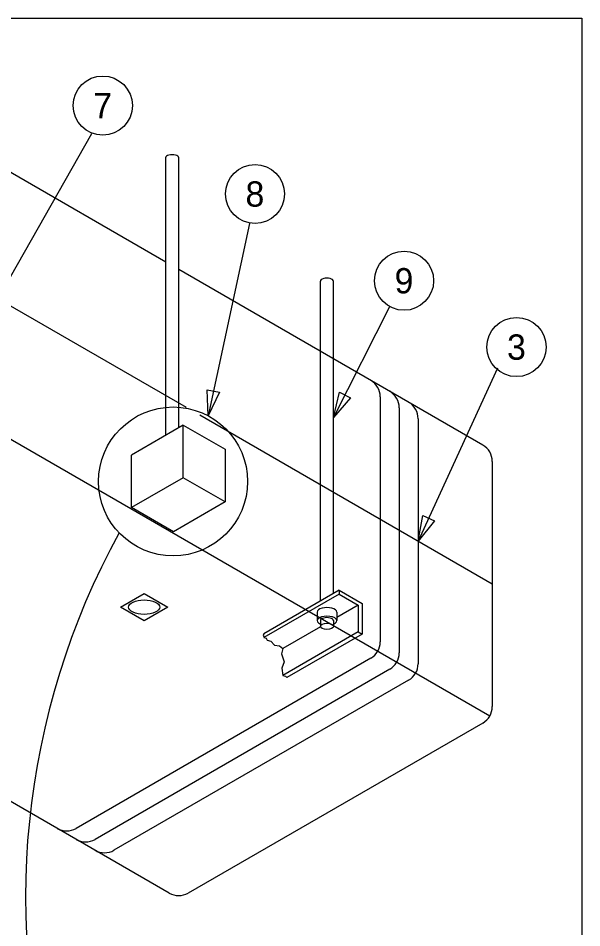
# Model space of a CAD drawing. Extents: x 10110.2 to 10159.4, y 10049.5 to 10140.5.
# Drawn here: x 10144.51 to 10159.36, y 10116.52 to 10140.51 of the extents above; entities that cross this region are included whole.
import ezdxf

# ---------------------------------------------------------------- set-up
doc = ezdxf.new("R2010")
doc.units = 0
for name, color, linetype in [('G-ANNO-SYMB', 7, 'Continuous'), ('G-DETL-GRID', 7, 'Continuous'), ('G-DETL-LINE', 7, 'Continuous'), ('G-DETL-TEXT', 7, 'Continuous')]:
    doc.layers.add(name, color=color, linetype=linetype)

msp = doc.modelspace()

# ---------------------------------------------------------------- linework, layer by layer
at = {"layer": 'G-ANNO-SYMB'}
for centre in [(10146.738, 10138.202), (10150.75, 10135.871), (10154.678, 10133.583), (10157.641, 10131.834)]:
    msp.add_circle(centre, 0.779, dxfattribs=at)
at = {"layer": 'G-DETL-GRID'}
msp.add_lwpolyline([(10110.22, 10140.505), (10159.362, 10140.505), (10159.362, 10095.005), (10110.22, 10095.005)], close=True, dxfattribs=at)
at = {"layer": 'G-DETL-LINE'}
for p, q in [((10148.395, 10134.077), (10142.598, 10137.424)), ((10148.395, 10134.077), (10142.598, 10137.424)), ((10148.395, 10129.51), (10148.395, 10136.827)), ((10148.395, 10129.51), (10148.395, 10136.827)), ((10148.74, 10129.709), (10148.74, 10136.827)), ((10148.947, 10130.239), (10142.598, 10133.904)), ((10148.947, 10130.239), (10142.598, 10133.904)), ((10156.752, 10129.252), (10148.74, 10133.878)), ((10156.752, 10129.252), (10148.74, 10133.878)), ((10152.474, 10131.722), (10152.474, 10133.573)), ((10152.474, 10131.722), (10152.474, 10133.573)), ((10152.819, 10131.523), (10152.819, 10133.573)), ((10152.819, 10131.523), (10152.819, 10133.573)), ((10152.474, 10125.141), (10152.474, 10131.722)), ((10152.474, 10125.141), (10152.474, 10131.722)), ((10152.819, 10125.34), (10152.819, 10131.523)), ((10152.819, 10125.34), (10152.819, 10131.523)), ((10154.049, 10130.524), (10154.049, 10124.062)), ((10154.049, 10130.524), (10154.049, 10124.062)), ((10154.549, 10130.235), (10154.549, 10123.773)), ((10154.549, 10130.235), (10154.549, 10123.773)), ((10156.935, 10122.107), (10142.888, 10130.217)), ((10156.935, 10122.107), (10142.888, 10130.217)), ((10157.002, 10125.588), (10149.292, 10130.039)), ((10157.002, 10125.588), (10149.292, 10130.039)), ((10148.859, 10129.778), (10147.493, 10128.989)), ((10148.859, 10129.778), (10147.493, 10128.989)), ((10155.049, 10129.947), (10155.049, 10123.485)), ((10155.049, 10129.947), (10155.049, 10123.485)), ((10147.493, 10127.602), (10147.493, 10128.989)), ((10147.493, 10127.602), (10147.493, 10128.989)), ((10157.002, 10128.819), (10157.002, 10122.357)), ((10157.002, 10128.819), (10157.002, 10122.357)), ((10148.859, 10128.39), (10147.493, 10127.602)), ((10148.859, 10128.39), (10147.493, 10127.602)), ((10148.598, 10126.964), (10147.493, 10127.602)), ((10148.598, 10126.964), (10147.493, 10127.602)), ((10149.963, 10127.753), (10148.598, 10126.964)), ((10149.963, 10127.753), (10148.598, 10126.964)), ((10148.487, 10117.44), (10134.623, 10125.445)), ((10148.487, 10117.44), (10134.623, 10125.445)), ((10152.97, 10125.427), (10150.981, 10124.279)), ((10152.97, 10125.427), (10150.981, 10124.279)), ((10152.97, 10125.427), (10153.574, 10125.078)), ((10152.97, 10125.427), (10152.97, 10125.323)), ((10152.97, 10125.427), (10153.574, 10125.078)), ((10152.97, 10125.427), (10152.97, 10125.323)), ((10152.97, 10125.323), (10150.981, 10124.175)), ((10152.97, 10125.323), (10150.981, 10124.175)), ((10152.97, 10125.323), (10153.47, 10125.034)), ((10152.97, 10125.323), (10153.47, 10125.034)), ((10153.47, 10125.034), (10152.905, 10124.708)), ((10153.47, 10125.034), (10152.905, 10124.708)), ((10153.47, 10125.034), (10153.47, 10124.328)), ((10153.47, 10125.034), (10153.47, 10124.328)), ((10153.574, 10125.078), (10153.574, 10124.268)), ((10153.574, 10125.078), (10153.574, 10124.268)), ((10152.387, 10124.847), (10152.387, 10124.622)), ((10152.387, 10124.847), (10152.387, 10124.622)), ((10152.905, 10124.847), (10152.905, 10124.622)), ((10152.905, 10124.847), (10152.905, 10124.622)), ((10152.474, 10124.622), (10152.474, 10124.472)), ((10152.474, 10124.622), (10152.474, 10124.472)), ((10152.819, 10124.622), (10152.819, 10124.472)), ((10152.819, 10124.622), (10152.819, 10124.472)), ((10150.981, 10124.279), (10150.962, 10124.227)), ((10150.981, 10124.279), (10150.962, 10124.227)), ((10152.476, 10124.46), (10151.481, 10123.886)), ((10152.476, 10124.46), (10151.481, 10123.886)), ((10153.47, 10124.328), (10151.481, 10123.18)), ((10153.47, 10124.328), (10151.481, 10123.18)), ((10153.574, 10124.268), (10151.586, 10123.12)), ((10153.574, 10124.268), (10151.586, 10123.12)), ((10153.47, 10124.328), (10153.574, 10124.268)), ((10153.47, 10124.328), (10153.574, 10124.268)), ((10150.962, 10124.227), (10150.979, 10124.202)), ((10150.962, 10124.227), (10150.979, 10124.202)), ((10150.979, 10124.202), (10150.992, 10124.185)), ((10150.979, 10124.202), (10150.992, 10124.185)), ((10150.992, 10124.185), (10150.981, 10124.175)), ((10150.992, 10124.185), (10150.981, 10124.175)), ((10150.981, 10124.175), (10151.043, 10124.158)), ((10150.981, 10124.175), (10151.043, 10124.158)), ((10151.043, 10124.158), (10151.073, 10124.111)), ((10151.043, 10124.158), (10151.073, 10124.111)), ((10151.073, 10124.111), (10151.163, 10124.082)), ((10151.073, 10124.111), (10151.163, 10124.082)), ((10151.163, 10124.082), (10151.263, 10123.973)), ((10151.163, 10124.082), (10151.263, 10123.973)), ((10151.263, 10123.973), (10151.395, 10123.957)), ((10151.263, 10123.973), (10151.395, 10123.957)), ((10151.395, 10123.957), (10151.481, 10123.886)), ((10151.395, 10123.957), (10151.481, 10123.886)), ((10151.481, 10123.886), (10151.45, 10123.745)), ((10151.481, 10123.886), (10151.45, 10123.745)), ((10153.799, 10123.629), (10146.033, 10119.146)), ((10153.799, 10123.629), (10146.033, 10119.146)), ((10151.45, 10123.745), (10151.518, 10123.541)), ((10151.45, 10123.745), (10151.518, 10123.541)), ((10151.518, 10123.541), (10151.458, 10123.371)), ((10151.518, 10123.541), (10151.458, 10123.371)), ((10154.299, 10123.34), (10146.533, 10118.857)), ((10154.299, 10123.34), (10146.533, 10118.857)), ((10151.458, 10123.371), (10151.481, 10123.18)), ((10151.458, 10123.371), (10151.481, 10123.18)), ((10154.799, 10123.052), (10147.033, 10118.568)), ((10154.799, 10123.052), (10147.033, 10118.568)), ((10151.481, 10123.18), (10151.549, 10123.162)), ((10151.481, 10123.18), (10151.549, 10123.162)), ((10151.549, 10123.162), (10151.586, 10123.12)), ((10151.549, 10123.162), (10151.586, 10123.12)), ((10156.752, 10121.924), (10148.987, 10117.44)), ((10156.752, 10121.924), (10148.987, 10117.44))]:
    msp.add_line(p, q, dxfattribs=at)
for points in [[(10149.963, 10127.753), (10148.859, 10128.39), (10148.859, 10129.778), (10149.963, 10129.14)], [(10149.963, 10127.753), (10148.859, 10128.39), (10148.859, 10129.778), (10149.963, 10129.14)], [(10147.207, 10124.979), (10147.828, 10125.338), (10148.449, 10124.979), (10147.828, 10124.62)], [(10147.207, 10124.979), (10147.828, 10125.338), (10148.449, 10124.979), (10147.828, 10124.62)]]:
    msp.add_lwpolyline(points, close=True, dxfattribs=at)
for centre, start, end in [((10153.549, 10130.524), 0, 60), ((10153.549, 10130.524), 0, 60), ((10154.049, 10130.235), 0, 60), ((10154.049, 10130.235), 0, 60), ((10154.549, 10129.947), 0, 60), ((10154.549, 10129.947), 0, 60), ((10156.502, 10128.819), 0, 60), ((10156.502, 10128.819), 0, 60), ((10153.549, 10124.062), 300, 360), ((10153.549, 10124.062), 300, 360), ((10154.049, 10123.773), 300, 360), ((10154.049, 10123.773), 300, 360), ((10154.549, 10123.485), 300, 360), ((10154.549, 10123.485), 300, 360), ((10156.502, 10122.357), 300, 360), ((10156.502, 10122.357), 300, 360), ((10145.783, 10119.579), 240, 300.0001), ((10145.783, 10119.579), 240, 300.0001), ((10146.283, 10119.29), 240, 300.0001), ((10146.283, 10119.29), 240, 300.0001), ((10146.783, 10119.002), 240, 300.0001), ((10146.783, 10119.002), 240, 300.0001), ((10148.737, 10117.874), 240, 300.0001), ((10148.737, 10117.874), 240, 300.0001)]:
    msp.add_arc(centre, 0.5, start, end, dxfattribs=at)
for centre, major_axis, start_param, end_param in [((10148.567, 10136.827), (-0.173, 0), 3.137491, 6.287287), ((10148.567, 10136.827), (-0.173, 0), 3.137491, 6.287287), ((10152.646, 10133.573), (-0.173, 0), 3.137491, 6.287287), ((10152.646, 10133.573), (-0.173, 0), 3.137491, 6.287287), ((10152.646, 10124.847), (-0.259, 0), 3.137491, 6.287287), ((10152.646, 10124.847), (-0.259, 0), 3.137491, 6.287287), ((10152.646, 10124.622), (-0.259, 0), 2.300516, 7.124262), ((10152.646, 10124.622), (-0.259, 0), 2.300516, 7.124262), ((10152.646, 10124.622), (-0.173, 0), 3.137491, 6.287287), ((10152.646, 10124.622), (-0.173, 0), 3.137491, 6.287287)]:
    msp.add_ellipse(centre, major_axis=major_axis, ratio=0.460797, start_param=start_param, end_param=end_param, dxfattribs=at)
for centre, major_axis in [((10147.828, 10124.979), (-0.413, 0)), ((10147.828, 10124.979), (-0.413, 0)), ((10152.646, 10124.472), (-0.173, 0)), ((10152.646, 10124.472), (-0.173, 0))]:
    msp.add_ellipse(centre, major_axis=major_axis, ratio=0.460797, dxfattribs=at)
at = {"layer": 'G-DETL-TEXT'}
for p, q in [((10146.44, 10137.459), (10143.032, 10131.459)), ((10146.44, 10137.459), (10143.032, 10131.459)), ((10150.6, 10135.093), (10149.516, 10130.025)), ((10150.6, 10135.093), (10149.516, 10130.025)), ((10154.307, 10132.91), (10152.819, 10129.977)), ((10154.307, 10132.91), (10152.819, 10129.977)), ((10157.143, 10131.283), (10155.049, 10126.716)), ((10157.143, 10131.283), (10155.049, 10126.716))]:
    msp.add_line(p, q, dxfattribs=at)
for points in [[(10149.818, 10130.642), (10149.516, 10130.025), (10149.492, 10130.711)], [(10149.818, 10130.642), (10149.516, 10130.025), (10149.492, 10130.711)], [(10153.269, 10130.496), (10152.819, 10129.977), (10152.972, 10130.647)], [(10153.269, 10130.496), (10152.819, 10129.977), (10152.972, 10130.647)], [(10155.478, 10127.252), (10155.049, 10126.716), (10155.175, 10127.391)], [(10155.478, 10127.252), (10155.049, 10126.716), (10155.175, 10127.391)]]:
    msp.add_lwpolyline(points, close=True, dxfattribs=at)
msp.add_circle((10148.591, 10128.291), 1.964, dxfattribs=at)
msp.add_arc((10164.714, 10117.308), 20.014, 151.243, 197.1832, dxfattribs=at)
msp.add_arc((10164.714, 10117.308), 20.014, 151.243, 197.1832, dxfattribs=at)

# ---------------------------------------------------------------- texts
at = {"layer": 'G-ANNO-SYMB'}
for s, p in [('7', (10146.488, 10137.868)), ('8', (10150.499, 10135.537)), ('9', (10154.428, 10133.25)), ('3', (10157.391, 10131.501))]:
    msp.add_text(s, height=0.667, dxfattribs=at).set_placement(p)

doc.saveas('drawing.dxf')
